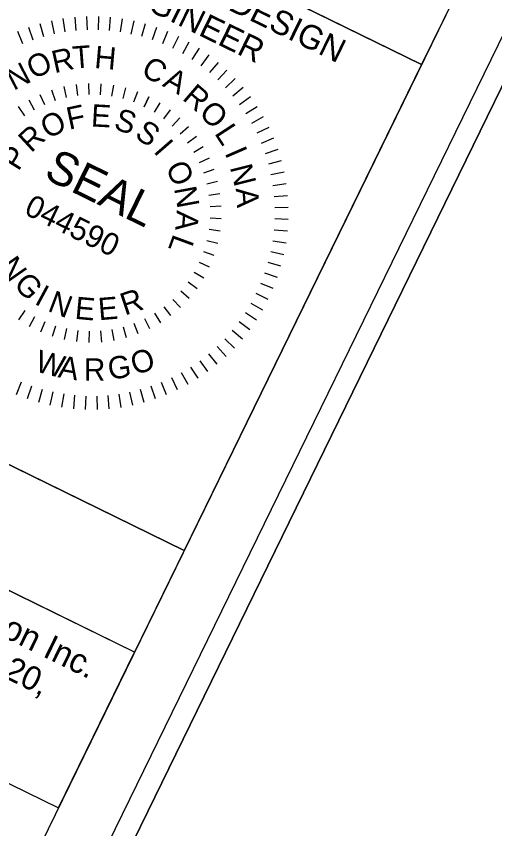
# Model space of a CAD drawing. Extents: x 1518247 to 1523638, y 635234 to 639927.
# Drawn here: x 1521833.1 to 1521932.7, y 637014.1 to 637183 of the extents above; entities that cross this region are included whole.
import ezdxf

# ---------------------------------------------------------------- set-up
doc = ezdxf.new("R2010")
doc.units = 0
for name, color, linetype in [('Default', 7, 'Continuous'), ('DTM TIN Hull White', 7, 'Continuous'), ('Sheet Plot Border Inside CELL', 7, 'Continuous'), ('Sheet Plot Border Outside CELL', 7, 'Continuous'), ('Sheet Sticker Exception Certification CELL', 7, 'Continuous'), ('Sheet Typical CELL', 7, 'Continuous')]:
    doc.layers.add(name, color=color, linetype=linetype)

msp = doc.modelspace()

# ---------------------------------------------------------------- linework, layer by layer
at = {"layer": 'Default'}
for points in [[(1521471.45, 636222.33), (1519958.68, 636962.19), (1520441.97, 637950.34), (1521954.73, 637210.48)], [(1521662.15, 637106.28), (1521841.85, 637018.4), (1521857.71, 637050.82), (1521678.01, 637138.71)]]:
    msp.add_lwpolyline(points, close=True, dxfattribs=at)
at = {"layer": 'DTM TIN Hull White'}
for p, q in [((1521840.39, 637182.12), (1521840.96, 637179.39)), ((1521842.81, 637182.56), (1521843.22, 637179.8)), ((1521845.26, 637182.85), (1521845.51, 637180.07)), ((1521847.73, 637182.99), (1521847.81, 637180.21)), ((1521850.2, 637182.98), (1521850.11, 637180.2)), ((1521852.66, 637182.83), (1521852.41, 637180.05)), ((1521855.11, 637182.53), (1521854.68, 637179.77)), ((1521857.54, 637182.07), (1521856.95, 637179.35)), ((1521835.62, 637180.8), (1521836.53, 637178.17)), ((1521837.98, 637181.53), (1521838.72, 637178.85)), ((1521859.94, 637181.48), (1521859.18, 637178.8)), ((1521862.29, 637180.73), (1521861.37, 637178.11)), ((1521833.31, 637179.94), (1521834.37, 637177.36)), ((1521864.6, 637179.85), (1521863.52, 637177.28)), ((1521866.85, 637178.83), (1521865.62, 637176.33)), ((1521869.03, 637177.68), (1521867.66, 637175.26)), ((1521871.14, 637176.4), (1521869.62, 637174.06)), ((1521873.17, 637174.99), (1521871.51, 637172.75)), ((1521875.11, 637173.46), (1521873.32, 637171.33)), ((1521876.95, 637171.82), (1521875.04, 637169.79)), ((1521878.69, 637170.07), (1521876.66, 637168.16)), ((1521842.95, 637168.42), (1521843.46, 637166.15)), ((1521845.52, 637168.87), (1521845.8, 637166.56)), ((1521848.11, 637169.06), (1521848.17, 637166.74)), ((1521850.72, 637169.01), (1521850.55, 637166.69)), ((1521853.3, 637168.7), (1521852.92, 637166.41)), ((1521880.32, 637168.21), (1521878.18, 637166.44)), ((1521838.01, 637166.79), (1521838.95, 637164.67)), ((1521840.44, 637167.72), (1521841.17, 637165.52)), ((1521855.85, 637168.15), (1521855.24, 637165.91)), ((1521858.32, 637167.35), (1521857.51, 637165.18)), ((1521835.68, 637165.63), (1521836.82, 637163.6)), ((1521860.71, 637166.32), (1521859.69, 637164.24)), ((1521859.69, 637164.24), (1521860.71, 637166.32)), ((1521862.99, 637165.06), (1521861.78, 637163.09)), ((1521881.84, 637166.27), (1521879.59, 637164.62)), ((1521833.48, 637164.25), (1521834.8, 637162.34)), ((1521865.14, 637163.59), (1521863.74, 637161.74)), ((1521883.24, 637164.23), (1521880.9, 637162.73)), ((1521867.13, 637161.92), (1521865.56, 637160.21)), ((1521884.51, 637162.12), (1521882.08, 637160.75)), ((1521868.96, 637160.06), (1521867.23, 637158.52)), ((1521885.65, 637159.93), (1521883.15, 637158.71)), ((1521870.6, 637158.04), (1521868.73, 637156.67)), ((1521886.66, 637157.67), (1521884.08, 637156.61)), ((1521872.03, 637155.87), (1521870.03, 637154.68)), ((1521887.53, 637155.36), (1521884.89, 637154.46)), ((1521873.25, 637153.56), (1521871.14, 637152.58)), ((1521888.26, 637153), (1521885.57, 637152.26)), ((1521874.24, 637151.16), (1521872.05, 637150.38)), ((1521888.84, 637150.6), (1521886.12, 637150.03)), ((1521874.99, 637148.67), (1521872.74, 637148.1)), ((1521889.28, 637148.17), (1521886.53, 637147.76)), ((1521875.5, 637146.11), (1521873.2, 637145.77)), ((1521889.57, 637145.72), (1521886.8, 637145.47)), ((1521875.76, 637143.53), (1521873.44, 637143.4)), ((1521889.72, 637143.26), (1521886.93, 637143.18)), ((1521875.77, 637140.92), (1521873.45, 637141.02)), ((1521889.7, 637140.79), (1521886.92, 637140.88)), ((1521875.52, 637138.33), (1521873.22, 637138.66)), ((1521889.55, 637138.32), (1521886.78, 637138.58)), ((1521875.03, 637135.77), (1521872.78, 637136.32)), ((1521889.25, 637135.87), (1521886.49, 637136.3)), ((1521874.3, 637133.27), (1521872.11, 637134.04)), ((1521888.8, 637133.44), (1521886.08, 637134.04)), ((1521873.32, 637130.86), (1521871.22, 637131.83)), ((1521888.2, 637131.05), (1521885.52, 637131.8)), ((1521872.12, 637128.55), (1521870.12, 637129.72)), ((1521887.46, 637128.69), (1521884.83, 637129.61)), ((1521868.87, 637127.79), (1521870.75, 637126.44)), ((1521886.58, 637126.39), (1521884.01, 637127.46)), ((1521869.08, 637124.33), (1521867.34, 637125.86)), ((1521885.56, 637124.14), (1521883.06, 637125.37)), ((1521865.28, 637120.78), (1521863.87, 637122.62)), ((1521867.27, 637122.46), (1521865.68, 637124.16)), ((1521884.4, 637121.95), (1521881.98, 637123.33)), ((1521833.63, 637119.91), (1521834.94, 637121.82)), ((1521863.15, 637119.3), (1521861.91, 637121.26)), ((1521883.12, 637119.85), (1521880.78, 637121.36)), ((1521835.84, 637118.54), (1521836.96, 637120.58)), ((1521838.18, 637117.4), (1521839.1, 637119.53)), ((1521860.88, 637118.02), (1521859.84, 637120.1)), ((1521881.71, 637117.82), (1521879.47, 637119.47)), ((1521840.61, 637116.48), (1521841.33, 637118.69)), ((1521843.13, 637115.81), (1521843.62, 637118.08)), ((1521845.69, 637115.38), (1521845.97, 637117.69)), ((1521848.29, 637115.2), (1521848.34, 637117.52)), ((1521850.9, 637115.27), (1521850.72, 637117.59)), ((1521853.48, 637115.59), (1521853.08, 637117.88)), ((1521856.02, 637116.16), (1521855.4, 637118.4)), ((1521858.49, 637116.98), (1521857.66, 637119.14)), ((1521880.19, 637115.88), (1521878.05, 637117.66)), ((1521878.54, 637114.03), (1521876.52, 637115.95)), ((1521876.79, 637112.29), (1521874.89, 637114.33)), ((1521874.94, 637110.66), (1521873.16, 637112.8)), ((1521872.99, 637109.14), (1521871.35, 637111.39)), ((1521870.95, 637107.74), (1521869.45, 637110.09)), ((1521866.65, 637105.33), (1521865.44, 637107.84)), ((1521868.84, 637106.47), (1521867.48, 637108.9)), ((1521833.11, 637104.41), (1521834.19, 637106.98)), ((1521835.42, 637103.53), (1521836.33, 637106.16)), ((1521862.08, 637103.46), (1521861.18, 637106.09)), ((1521864.39, 637104.33), (1521863.34, 637106.9)), ((1521837.77, 637102.79), (1521838.53, 637105.47)), ((1521840.17, 637102.19), (1521840.76, 637104.91)), ((1521842.6, 637101.73), (1521843.03, 637104.49)), ((1521845.04, 637101.43), (1521845.3, 637104.21)), ((1521847.51, 637101.28), (1521847.6, 637104.06)), ((1521849.98, 637101.27), (1521849.9, 637104.06)), ((1521852.45, 637101.41), (1521852.2, 637104.19)), ((1521854.9, 637101.7), (1521854.48, 637104.46)), ((1521857.32, 637102.14), (1521856.75, 637104.87)), ((1521859.73, 637102.73), (1521858.98, 637105.41))]:
    msp.add_line(p, q, dxfattribs=at)
at = {"layer": 'Sheet Plot Border Inside CELL'}
msp.add_lwpolyline([(1521940.83, 637192.29), (1520443.78, 637924.46), (1519980.23, 636976.65), (1521477.27, 636244.48)], close=True, dxfattribs=at)
at = {"layer": 'Sheet Plot Border Outside CELL'}
msp.add_lwpolyline([(1521954.73, 637210.48), (1520441.97, 637950.34), (1519958.68, 636962.19), (1521471.45, 636222.33)], close=True, dxfattribs=at)
at = {"layer": 'Sheet Sticker Exception Certification CELL'}
for p, q in [((1521688.34, 637159.82), (1521868.03, 637071.93)), ((1521857.71, 637050.82), (1521678.01, 637138.71)), ((1521868.03, 637071.92), (1521857.7, 637050.81))]:
    msp.add_line(p, q, dxfattribs=at)
at = {"layer": 'Sheet Typical CELL'}
for points in [[(1521928.48, 637195.49), (1520581, 637854.51), (1520119.69, 636911.28), (1521467.16, 636252.26)], [(1521748.77, 637283.38), (1521928.48, 637195.49), (1521917.47, 637172.99), (1521737.76, 637260.88)], [(1521827.64, 637216.92), (1521917.47, 637172.99), (1521868.05, 637071.93), (1521778.21, 637115.86)]]:
    msp.add_lwpolyline(points, close=True, dxfattribs=at)

# ---------------------------------------------------------------- texts
at = {"layer": 'Default'}
for s, height, p in [('Johnson, Mirmiran, & Thompson Inc.', 5.1112, (1521747.95, 637094.21)), ('2550 West Tyvola Road, Suite 120,', 4.9652, (1521744.66, 637087.47))]:
    msp.add_text(s, height=height, rotation=333.9377, dxfattribs=at).set_placement(p)
at = {"layer": 'DTM TIN Hull White'}
for s, height, rotation, p in [('T', 4.64, 4.3843, (1521844.98, 637172.13)), ('H', 4.64, 354.9524, (1521849.23, 637172.3)), ('O', 4.64, 25.602, (1521836.65, 637169.85)), ('R', 4.64, 12.5453, (1521841.04, 637171.18)), ('N', 4.64, 27.5614, (1521832.53, 637167.5)), ('C', 4.64, 331.2417, (1521858.83, 637170.92)), ('A', 4.64, 331.2417, (1521863.34, 637168.6)), ('R', 4.64, 319.2324, (1521867.46, 637165.82)), ('O', 4.64, 316.1756, (1521870.9, 637162.64)), ('F', 4.64, 12.1253, (1521844.08, 637159.42)), ('E', 4.64, 356.8291, (1521848.57, 637160.14)), ('S', 4.64, 341.5328, (1521853.18, 637159.66)), ('O', 4.64, 27.4216, (1521839.66, 637157.42)), ('R', 4.64, 42.7178, (1521836.18, 637154.49)), ('S', 4.64, 326.2366, (1521857.51, 637157.96)), ('L', 4.64, 303.0393, (1521874.23, 637158.71)), ('I', 4.64, 310.9403, (1521861.5, 637154.89)), ('P', 4.64, 58.0141, (1521833.52, 637150.67)), ('SEAL', 6.965, 333.8847, (1521838.57, 637149.5)), ('I', 4.64, 293.4638, (1521876.41, 637154.65)), ('O', 4.64, 295.6441, (1521864.07, 637151.62)), ('N', 4.64, 284.1693, (1521877.53, 637151.66)), ('N', 4.64, 280.3478, (1521865.91, 637147.26)), ('A', 4.64, 274.4018, (1521878.77, 637147.23)), ('044590', 4.64, 333.8847, (1521834.49, 637142)), ('A', 4.64, 265.0516, (1521866.52, 637142.73)), ('L', 4.64, 249.7554, (1521865.85, 637137.94)), ('N', 4.64, 304.8099, (1521829.23, 637131.03)), ('G', 4.64, 313.5761, (1521832.35, 637127.08)), ('I', 4.64, 331.6709, (1521836.66, 637123.31)), ('N', 4.64, 339.3006, (1521839.42, 637121.79)), ('R', 4.64, 18.4496, (1521855.69, 637120.77)), ('E', 4.64, 354.6926, (1521845.15, 637120.13)), ('E', 4.64, 4.6785, (1521850.3, 637119.81)), ('W', 4.64, 345.1793, (1521836.78, 637109.25)), ('G', 4.64, 8.3265, (1521852.49, 637107.42)), ('O', 4.64, 17.2091, (1521857.74, 637108.38)), ('A', 4.64, 350.5013, (1521841.62, 637107.98)), ('R', 4.64, 359.5039, (1521847.13, 637107.27))]:
    msp.add_text(s, height=height, rotation=rotation, dxfattribs=at).set_placement(p)
at = {"layer": 'Sheet Typical CELL'}
for s, height, p in [('PAVEMENT DESIGN', 5.0001, (1521842.29, 637201.47)), ('ENGINEER', 5, (1521851.77, 637188.53))]:
    msp.add_text(s, height=height, rotation=333.9377, dxfattribs=at).set_placement(p)

doc.saveas('drawing.dxf')
